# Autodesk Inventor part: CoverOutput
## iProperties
Part Number: CoverOutput
Document SubType Name: Modeling
Created: 2003-11
Designer: ales
Manufacturer: Standard
Standards Organization: Custom
Density: 1 g/cm^3
Mass: 37.952 g
Surface Area: 155.781 cm^2
Volume: 37.952 cm^3
Control State: 0
Master: False
Checked Out: False
Shininess: 64.0
Length Units: 11269
Angle Units: 11279
Time Units: 11290
Mass Units: 11283
Length Display Precision: 3
Angle Display Precision: 2
Compacted: True
Density: 0.0
Volumn: 0.0
Area: 0.0
PropertySet Name: Model Information
Author: ales
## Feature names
1. Revolution1
2. Fillet1
3. Chamfer1
